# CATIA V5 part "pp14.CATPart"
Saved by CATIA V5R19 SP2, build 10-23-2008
Part number: pp14
Publications: "Line.1", "Line.2", "Point.5", "Point.6", "Line.3", "Plane.1"
Bounding box of the stored display mesh (mm): x 0 to 0, y -190 to 0, z -25 to 25
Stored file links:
  C:\Users\Welcome\Documents\thinkm2\pp14.CATPart
  C:\Users\Welcome\Documents\thinkm2\Brasmeca.CATProduct
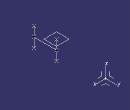
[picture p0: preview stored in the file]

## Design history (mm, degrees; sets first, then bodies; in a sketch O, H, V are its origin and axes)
AxisSystem1: origin (0, 0, 0), X (1, 0, 0), Y (0, 1, 0), Z (0, 0, 1)
Set1
  Point1 to Point4: linked copy from another document
Body1 (main body)
  Line1: type PtPt, FirstPoint Point1, SecondPoint Point2
  Line2: type PtPt, FirstPoint Point3, SecondPoint Point4
  Point5: type OnCurve, Support Line1, Length 25
  Point6: type OnCurve, Support Line2, Length 25
  Line3: type PtPt, FirstPoint Point5, SecondPoint Point6
  Plane1: type Normal, Curve Line1, RefPoint Point1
